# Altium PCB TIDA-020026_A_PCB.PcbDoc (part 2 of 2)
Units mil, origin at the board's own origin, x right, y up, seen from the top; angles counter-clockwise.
Board outline 2952.76 x 2952.76 mil, 2 copper layers (Top Layer, Bottom Layer), stack 62 mil thick; 75 components, 57 nets, 258 pads, 285 vias.
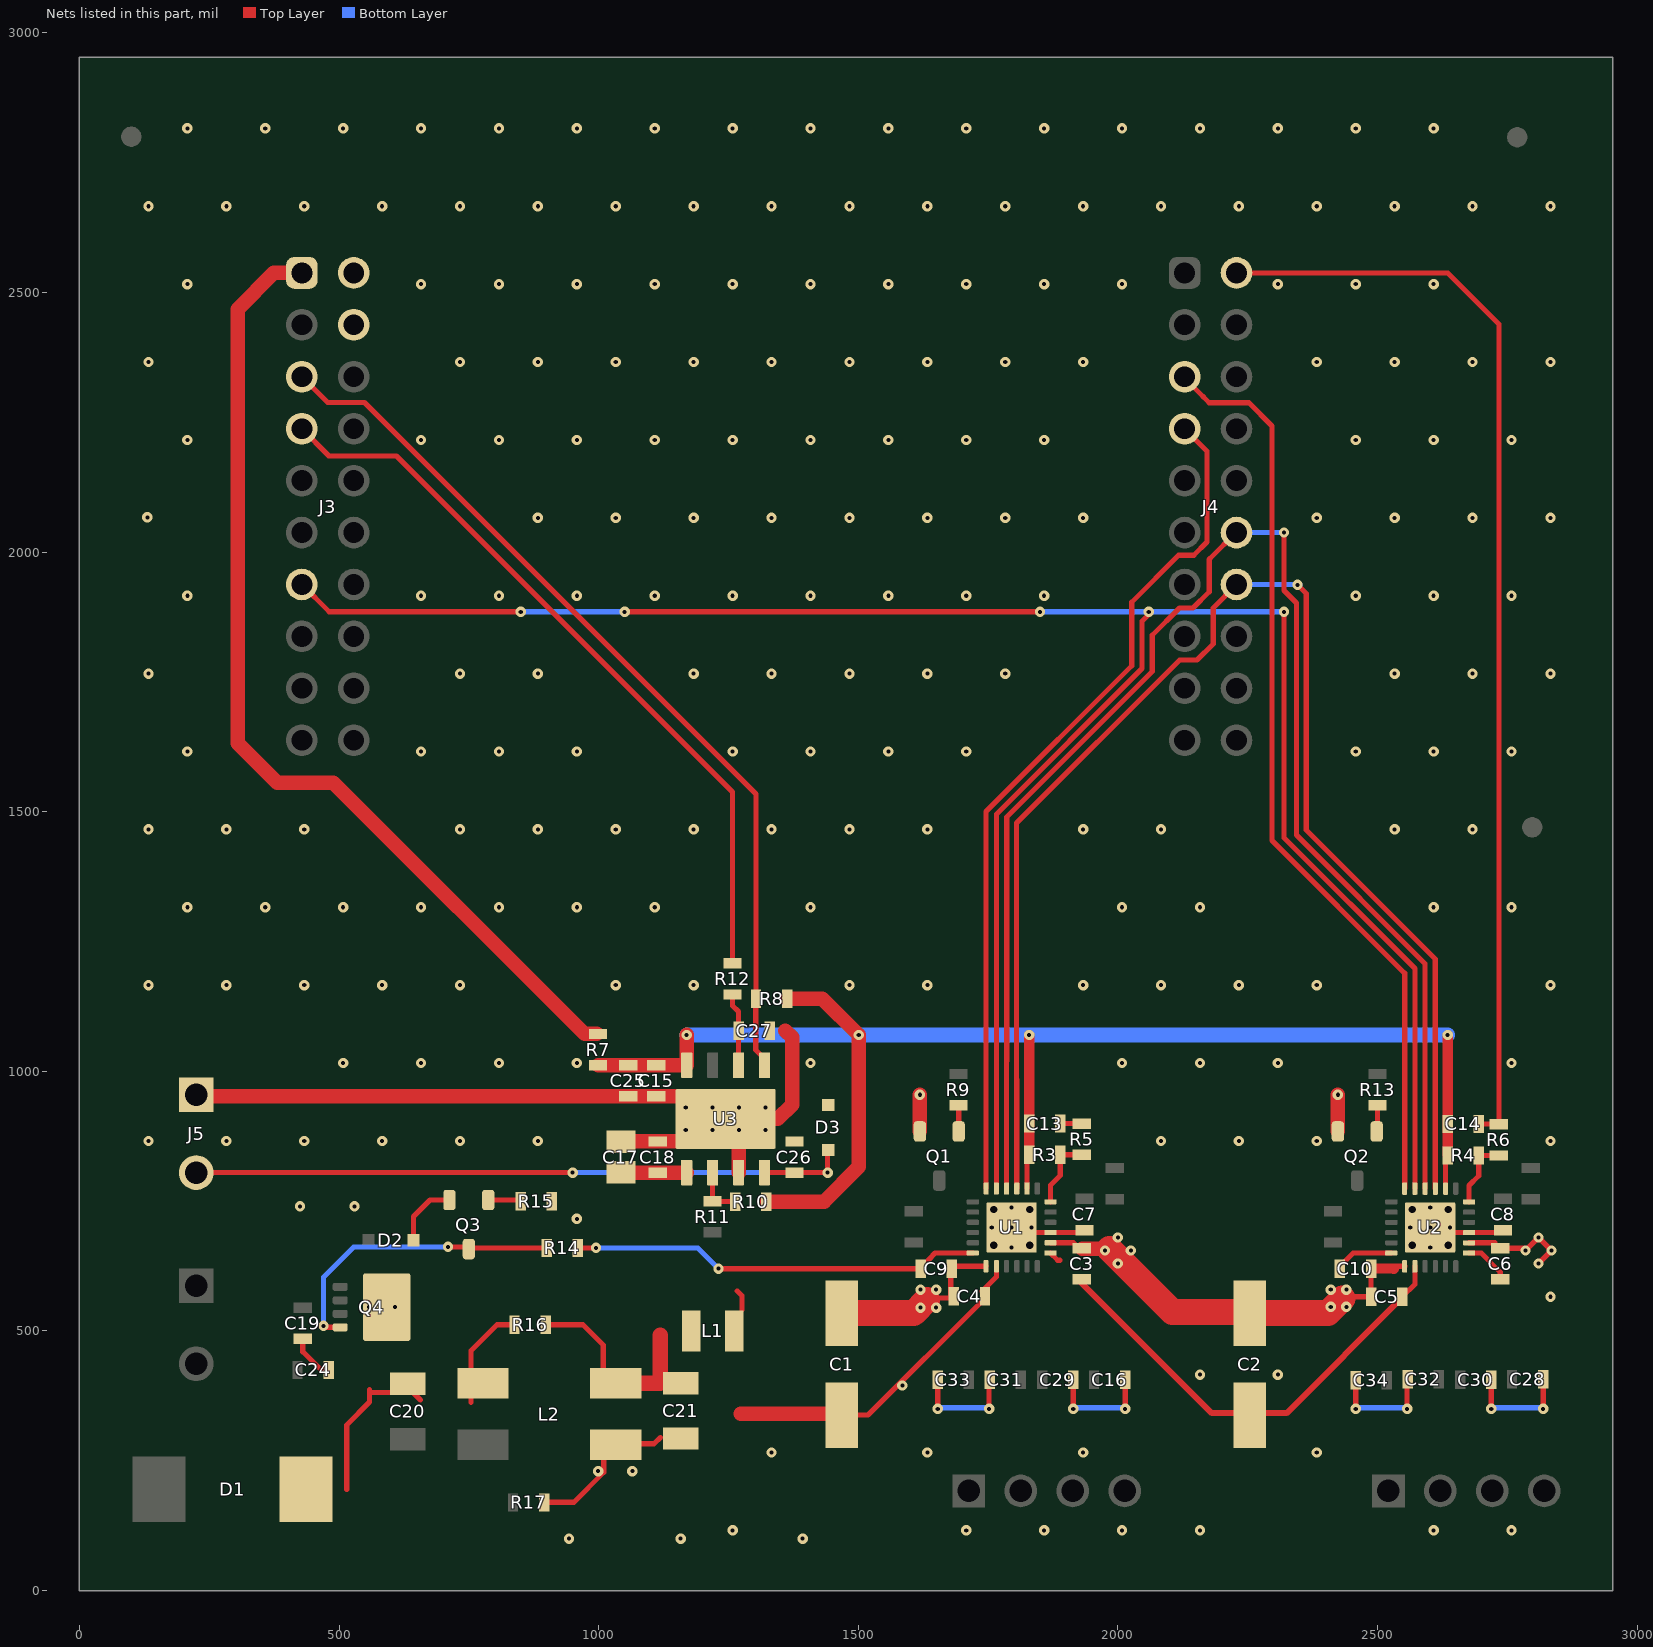
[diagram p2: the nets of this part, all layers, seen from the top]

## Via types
v1: diameter 19.87, hole 7.87, Top Layer to Bottom Layer, tented both sides, 257 vias
v2: diameter 19.68, hole 7.87, Top Layer to Bottom Layer, 16 vias
v3: diameter 26, hole 14, Top Layer to Bottom Layer, 8 vias
v4: diameter 19.68, hole 7.87, Top Layer to Bottom Layer, tented both sides, 4 vias

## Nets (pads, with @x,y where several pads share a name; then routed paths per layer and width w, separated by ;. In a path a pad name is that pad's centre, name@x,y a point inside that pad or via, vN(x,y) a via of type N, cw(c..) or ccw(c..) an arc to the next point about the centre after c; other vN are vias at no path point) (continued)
GND: C1.2 C2.2 C3.2 C4.2 C5.2 C6.2 C7.2 C8.2 C13.2 C14.2 C15.2 C16.1 C17.2 C18.2 C21.2 C25.2 C26.2 C27.2 C28.1 C29.1 C30.1 C31.1 C32.1 C33.1 C34.1 D3.1 J3.4 J4.2 J5.1 L2.3 Q1.2 Q2.2 R5.1 R6.1 R15.1 R17.2 U1.2 U1.7 U1.9 U1.25@1795.47,699.47 U2.2 U2.7 U2.9 U2.25@2601.47,699.34 U3.3 U3.9@1244.52,908.35 | length 7042.7
  Top Layer w10: R17.2@895,170 952,170 1010,228 1010,282.9 1009.95,282.94 1106.8,282.94 1118.85,295 ; U3.9@1222.58,886.42 U3.9@1244.52,908.35 ; C1.2@1480.71,350.29 1493,338 1519,338 C4.2@1743,562 ; v1@1653,352 C33.1@1653,404 ; C4.2@1738.12,576.56 1765.94,604.39 U1.2@1765.94,624.54 ; v1@1752,351 C31.1@1752,403 ; U1.25@1765.94,671.94 U1.25@1794.41,700.41 ; U1.25@1794.5,700.5 U1.25@1795,701 ; U1.25@1795,700 1805.5,689.5 C7.2@1925.63,689.5 ; U1.7@1870.28,650.13 1884.06,636.35 1888.2,636.35 ; C13.2@1886.61,903.2 C13.2@1888.2,901.61 ; C13.2@1890.47,899.34 R5.1@1930.47,899.34 ; v1@1914,353 C29.1@1914,405 ; v1@2014,352 C16.1@2014,405 ; J4.2@2228.47,2537.65 2635.35,2537.65 2734.07,2438.93 2734.07,898.67 C14.2@2695,898.67 ; v1@2458,352 C34.1@2458,404 ; C5.2@2547.62,565.82 2571.94,590.14 U2.2@2571.94,624.54 ; v1@2557,351 C32.1@2557,403 ; U2.25@2612.5,689.5 U2.9@2676.28,689.5 C8.2@2731.63,689.5 ; U2.7@2676.28,650.13 2699.6,650.13 2736.47,613.26 C6.2@2736.47,599.34 ; v1@2719,353 C30.1@2719,405 ; v1@2819,352 C28.1@2819,405
  Top Layer w11.81: C3.2@1921,602 2181,342 2325,342 2547.62,564.62 C5.2@2547.62,565.82 ; C5.2@2545.67,565.82 C5.2@2545.67,568.2 ; U2.25@2571.94,669.94 U2.25@2602,700
  Top Layer w28: J5.1@228,952 C25.2@1057,952 C15.2@1111,952 1200.87,952 U3.9@1244.52,908.35 ; C17.2@1043,864.53 1043.47,865 C18.2@1114,865 1200,865 U3.9@1220.31,885.31 ; U3.9@1268.14,884.73 U3.9@1244.52,908.35 ; U3.3@1269.52,805.01 U3.9@1269.52,883.35 ; 1273.68,340.33 1463.33,340.33 C1.2@1466,343 ; 1359.48,1078.35 1372.47,1065.36 1372.47,935.65 1345.17,908.35 U3.9@1244.52,908.35 ; Q1.2@1618.6,884.24 v1(1618.6,955) ; Q2.2@2423.6,884.24 v1(2423.6,955)
  Bottom Layer w10: v1@1653,352 v1@1750,352 ; v1@1914,352 v1@2014,352 ; v1@2458,352 v1@2555,352 ; v1@2719,352 v1@2819,352
  other v1: 943,100 1158,100 1393,100 1258,116 1708,116 1858,116 2008,116 2158,116 2608,116 2758,116 999,230 1065,230.12 1333,266 1633,266 1933,266 2383,266 1653,350 1752,350 1914,350 2014,350 2458,350 2557,350 2719,350 2819,350 1585,395 2158,416 2308,416 2833,566 958,716 425,740 530,740 133,866 283,866 433,866 583,866 733,866 883,866 2083,866 2233,866 2383,866 2833,866 508,1016 658,1016 808,1016 958,1016 1408,1016 2008,1016 2158,1016 2308,1016 2758,1016 133,1166 283,1166 433,1166 583,1166 733,1166 1033,1166 1183,1166 1483,1166 1633,1166 1933,1166 2083,1166 2233,1166 2383,1166 2833,1166 208,1316 358,1316 508,1316 658,1316 808,1316 958,1316 1108,1316 1408,1316 2008,1316 2158,1316 2608,1316 2758,1316 133,1466 283,1466 433,1466 733,1466 883,1466 1033,1466 1183,1466 1333,1466 1483,1466 1633,1466 1933,1466 2083,1466 2533,1466 2683,1466 208,1616 658,1616 808,1616 958,1616 1258,1616 1408,1616 1558,1616 1708,1616 2458,1616 2608,1616 2758,1616 133,1766 733,1766 883,1766 1183,1766 1333,1766 1483,1766 1633,1766 1783,1766 2533,1766 2683,1766 2833,1766 208,1916 658,1916 808,1916 958,1916 1108,1916 1258,1916 1408,1916 1558,1916 1708,1916 1858,1916 2458,1916 2608,1916 2758,1916 883,2066 1033,2066 1183,2066 1333,2066 1483,2066 1633,2066 1783,2066 1933,2066 2383,2066 2533,2066 2683,2066 2833,2066 131,2067 208,2216 658,2216 808,2216 958,2216 1108,2216 1258,2216 1408,2216 1558,2216 1708,2216 1858,2216 2458,2216 2608,2216 2758,2216 133,2366 733,2366 883,2366 1033,2366 1183,2366 1333,2366 1483,2366 1633,2366 1783,2366 1933,2366 2383,2366 2533,2366 2683,2366 2833,2366 208,2516 658,2516 808,2516 958,2516 1108,2516 1258,2516 1408,2516 1558,2516 1708,2516 1858,2516 2008,2516 2308,2516 2458,2516 2608,2516 133,2666 283,2666 433,2666 583,2666 733,2666 883,2666 1033,2666 1183,2666 1333,2666 1483,2666 1633,2666 1783,2666 1933,2666 2083,2666 2233,2666 2383,2666 2533,2666 2683,2666 2833,2666 208,2816 358,2816 508,2816 658,2816 808,2816 958,2816 1108,2816 1258,2816 1408,2816 1558,2816 1708,2816 1858,2816 2008,2816 2158,2816 2308,2816 2458,2816 2608,2816
  other v2: 1795.47,661.08 2601.47,660.96 1757.09,699.47 1795.47,699.47 1833.86,699.47 2563.09,699.34 2601.47,699.34 2639.86,699.34 1795.47,737.86 2601.47,737.73 1218.93,886.7 1270.11,886.7 1218.93,930.01 1270.11,930.01
  other v3: 1761,665 1830,665 2567,664.87 2636,664.87 1761,734 1830,734 2567,733.87 2636,733.87
  other v4: 1167.75,886.7 1321.29,886.7 1167.75,930.01 1321.29,930.01
"LIN Bus": C26.1 D3.2 J5.2 U3.4 | length 1378.7
  Top Layer w10: J5.2@225,805 v1(950,805) ; U3.4@1320,804.53 U3.4@1319.52,805.01 1372.01,805.01 C26.1@1373,806 ; C26.1@1377,805 v1(1441,805) 1441,847.69 D3.2@1442,848.69
  Bottom Layer w10: v1(950,805) v1(1441,805)
LP_+3V3: J3.1 R7.2 | length 1911.3
  Top Layer w28: J3.1@428.47,2537.65 374.65,2537.65 305,2468 305,1632 381,1556 489,1556 973,1072 R7.2@996,1072
LP_+5V: J3.2
NetC19_2: C19.2 C24.1 | length 89.5
  Top Layer w10: C19.2@430,485 430,460 430.71,460 465.71,425 C24.1@480,425
NetC21_1: C21.1 L1.1 L2.4 R16.2 | length 394.7
  Top Layer w10: R16.2@898,512 970,512 1009,473 L2.4@1009,409.39 ; L2.4@998,396 L2.4@998,398.39
  Top Layer w28: 1118.69,491.69 1119,492
  Top Layer w30: L2.4@1011,402 1013.61,399.39 1118.69,399.39 1118.69,491.69
NetC27_1: C27.1 R12.1 U3.6 | length 141.1
  Top Layer w10: R12.1@1258,1148 1258,1126.52 1269.52,1115 C27.1@1269.52,1078.35 U3.6@1269.52,1011.7
NetD2_2: D2.2 Q3.2 | length 127.9
  Top Layer w10: D2.2@643.31,675 643.31,720.5 675.05,752.24 Q3.2@712.6,752.24
NetQ1_1: Q1.1 R9.2 | length 50.9
  Top Layer w10: R9.2@1693,935 1693.4,934.6 Q1.1@1693.4,884.24
NetQ2_1: Q2.1 R13.2 | length 51.4
  Top Layer w10: Q2.1@2498.4,884.24 2500,885.84 R13.2@2500,935
NetQ3_1: Q3.1 R15.2 | length 63.5
  Top Layer w10: Q3.1@787.4,752.24 847.76,752.24 R15.2@850,750
NetQ3_3: Q3.3 Q4.4 R14.1 | length 583.9
  Top Layer w10: v1(470,510) 472.98,507.02 Q4.4@502.24,507.02 ; v1(710,662) 745.76,662 Q3.3@750,657.76 752.24,660 R14.1@900,660
  Bottom Layer w10: v1(470,510) 470,603.55 528.45,662 v1(710,662)
NetR10_1: R10.1 R11.1 U3.2 | length 100.3
  Top Layer w10: U3.2@1220,804.53 U3.2@1219.52,805.01 1219.52,749.53 1262.94,749.53 R10.1@1263.47,749
RXD: J3.5 R8.1 U3.5 | length 1736.9
  Top Layer w10: J3.5@428.47,2337.65 478.19,2287.93 549.07,2287.93 1303.04,1533.96 R8.1@1303.04,1140 1302.65,1139.6 1302.65,1041 1319.52,1024.13 U3.5@1319.52,1011.7
SCLK: J3.13 U1.17 U2.17 | length 4369.7
  Top Layer w10: J3.13@419,1927 420,1927 J3.13@431.5,1915.5 ; J3.13@428.47,1937.65 481.13,1885 v1(850,1885) ; v1(1050,1885) v1(1850,1885) ; U1.17@1765.94,774.15 1765.94,1495.09 2046.48,1775.62 2046.48,1867 v1@2059.47,1880 ; v1@2320,1880 2320,1450 2571.94,1198.06 U2.17@2571.94,774.15
  Bottom Layer w10: v1(850,1885) v1(1050,1885) ; v1@1049,1880 v1@1050,1881 ; v1(1850,1885) v1(2059.47,1885) v1(2320,1885)
SDI: J4.12 U1.16 U2.16 | length 2930
  Top Layer w10: U1.16@1785.63,774.15 1786,1261 1786,1489.86 2066,1769.86 2066,1840 2118.65,1892.65 2144.83,1892.65 2175.96,1923.79 2175.96,1985.14 ; 2176.96,1987.14 J4.12@2229.47,2039.65 ; v1(2320,2037.93) 2320,1926 2344,1902 2344,1455 2591.63,1207.37 U2.16@2591.63,774.15
  Bottom Layer w10: J4.12@2228.47,2037.65 2228.74,2037.93 v1(2320,2037.93)
SDO: J4.14 U1.15 U2.15 | length 2754.1
  Top Layer w10: U1.15@1805.31,774.15 1805,1199 1805,1478 2119,1792 2152.47,1792 2183.47,1823 2183.47,1892.65 J4.14@2228.47,1937.65 ; v1(2346,1937) 2362.87,1920.13 2362.87,1465.13 2611.31,1216.69 U2.15@2611.31,774.15
  Bottom Layer w10: J4.14@2228.47,1937.65 2350.35,1937.65 v1@2351,1937
STEP_U1: J4.7 U1.18 | length 1674.9
  Top Layer w10: U1.18@1746.26,774.15 1746.26,1500.68 2026.6,1781.02 2026.6,1903.6 2117,1994 2146.18,1994 2171.86,2019.68 2171.86,2194.27 J4.7@2128.47,2237.65
STEP_U2: J4.5 U2.18 | length 1781
  Top Layer w10: J4.5@2128.47,2337.65 2128.47,2335 2164.44,2299.03 2175.82,2287.65 ; 2178.65,2287.65 2252.35,2287.65 2297,2243 2297,1444.32 2552.26,1189.06 U2.18@2552.26,774.15
TXD: J3.7 R12.2 | length 1450
  Top Layer w10: J3.7@428.47,2237.65 480,2186.13 480,2185 611,2185 1258,1538 R12.2@1258,1208
V_supply: C20.1 D1.1 L2.1 Q4.5 Q4.6 Q4.7 Q4.8 Q4.9@592.01,546.02 R16.1 | length 527.9
  Top Layer w10: 514.73,195 514.73,319.21 558.56,363.04 558.56,381.76 ; 558.56,387.53 558.56,381.76 ; C20.1@636.56,387.53 657,367.09 ; C20.1@642.24,381.76 558.56,381.76 ; 754.05,362.05 754.05,401.06 754.05,462.05 804,512 R16.1@838,512
  other v2: 557.76,546.02 607.95,546.02
VCC_3V3: C13.1 C14.1 C15.1 C25.1 R3.2 R4.2 R7.1 R8.2 R10.2 U1.14 U2.14 U3.8 | length 2911.1
  Top Layer w10: U1.14@1825,774.15 R3.2@1825,840.24 ; U2.14@2631,774.15 R4.2@2631,835.6
  Top Layer w20: R3.2@1829,839.34 C13.1@1829,899.34 v1(1829,1070) ; R4.2@2635,839.6 2635,898.02 v1(2635,1070)
  Top Layer w28: R7.1@999,1012 C25.1@1057,1012 C15.1@1111,1012 1169.22,1012 U3.8@1169.52,1011.7 v1(1169.52,1070) ; R10.2@1322.53,749 1434,749 1501,816 v1(1501,1070) 1431,1140 R8.2@1362.57,1140
  Bottom Layer w28: v1(1169.52,1070) v1(1501,1070) v1(1829,1070) v1(2635,1070) v1@2635.41,1070
VCP_U1: C9.2 R14.2 U1.24 | length 788.2
  Top Layer w10: R14.2@960,660 v1(995,660) ; v1(1231,620) C9.2@1617.59,620 ; C9.2@1620,620 1647.85,650.26 U1.24@1720.67,650.26 U1.24@1720.67,650.13
  Bottom Layer w10: v1(995,660) 1191,660 v1(1231,620)
VCP_U2: C10.2 U2.24 | length 116.6
  Top Layer w10: C10.2@2422.78,619.88 2453.15,650.26 2526.67,650.26 U2.24@2526.67,650.13
VM: C1.1 C2.1 C3.1 C4.1 C5.1 C6.1 C9.1 C10.1 C17.1 C18.1 L1.2 U1.1 U1.8 U2.1 U2.8 U3.1 | length 1518.8
  Top Layer w10: C17.1@1043,805.47 1043,804 C17.1@1044,805 ; 1267,577 1276,568 1276,541 ; 1639.22,563.52 1675.57,563.52 1678.12,566.07 1678.12,619.24 1677.47,619.88 1682.13,624.54 U1.1@1746.26,624.54 ; U1.8@1870.28,669.82 1914.23,669.82 C3.1@1924.71,659.34 ; 2435.82,565.82 C5.1@2487.62,565.82 ; C5.1@2485.32,563.52 C5.1@2487.62,565.82 ; C10.1@2487.56,619.88 2487.56,566.44 C5.1@2488,566 ; C10.1@2488,621 C10.1@2488.75,620.25 ; 2517.57,620.25 2514.43,620.25 2518.71,624.54 ; 2531.52,619.88 2536.18,624.54 U2.1@2552.26,624.54 ; U2.8@2676.28,669.82 2726,669.82 ; C6.1@2736.47,659.34 2780.66,659.34 v1(2785,655) v1(2810,680) v1(2835,655) v1(2810,630)
  Top Layer w11.81: C3.1@1924.71,659.34 C3.1@1930.47,659.34 C3.1@1931.55,658.27
  Top Layer w20: C10.1@2488.75,620.25 2514.43,620.25 ; 2517.57,620.25 2531.52,619.88
  Top Layer w28: C17.1@1044,805 C18.1@1114,805 U3.1@1169.52,805.01 ; C3.1@1931.55,658.27 v1@1983.71,658.27
  Top Layer w50: C1.1@1468,534.43 1606.43,534.43 1632,560 ; v1@1983.71,658.27 2104.98,537 C2.1@2248,537 ; C2.1@2254,534.43 2404.43,534.43 2433,563
  other v1: 1620,545 1650,545 2410,546.38 2440,546.38 1620,579.69 1650,579.69 2410,579.69 2440,579.69 2000,630 1975,655 2025,655 2000,680
VREF_U1: R3.1 R5.2 U1.12 | length 140
  Top Layer w10: U1.12@1870.28,748.56 1870.28,780.78 1889,799.5 R3.1@1889,839.34 R5.2@1930.47,839.34
VREF_U2: R4.1 R6.2 U2.12 | length 135.6
  Top Layer w10: U2.12@2676.28,748.56 2676.28,780.28 2695,799 R4.1@2695,838.02 R6.2@2733.42,838.02
pads on no net: FID1.1 FID2.1 FID3.1 J3.3 J3.6 J3.8 J3.9 J3.10 J3.11 J3.12 J3.14 J3.16 J3.17 J3.18 J3.19 J3.20 J4.4 J4.8 J4.10 J4.13 J4.15 J4.17 Q4.9@555,485 Q4.9@555,546.02 Q4.9@555,607.05 Q4.9@578.03,523.58 Q4.9@578.03,568.46 Q4.9@583.94,546.02 U1.25@1770.28,674.27 U1.25@1770.28,724.67 U1.25@1820.67,674.27 U1.25@1820.67,724.67 U2.25@2576.28,674.15 U2.25@2576.28,724.54 U2.25@2626.67,674.15 U2.25@2626.67,724.54 U3.9@1244.52,908.35
copper on no net: | length 10
  Top Layer w10: 2128.47,1727.65 2128.47,1737.65

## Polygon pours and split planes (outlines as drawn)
GND on Top Layer "TOP_LAYER_GND_P104" (solid, remove dead copper, pour order 104): 6.81,2952.29 6.81,674.13 671.81,674.13 875,674.13 875,25.08 2952.76,25.08 2952.04,2948.01
VM on Top Layer "TOP_LAYER_VM_P088" (solid, remove dead copper, pour order 88): 2847,695 2847,620 2764.1,620.9 2717.79,667.21 2717.79,674.77 2765.83,674.77 2781,695
BAT+ on Top Layer "TOP_LAYER_BAT+_P086" (solid, remove dead copper, pour order 86): 25,514 501,514 501,473 654.35,473 654.35,635.38 365,635.38 25,635.38
NetC21_1 on Top Layer "TOP_LAYER_NETC21_1_P082" (solid, remove dead copper, pour order 82): 875,635 875,350 1205,350 1205,635
BAT- on Top Layer "TOP_LAYER_BAT-_P094" (solid, remove dead copper, pour order 94): 251,851 376,851 376,783 251,783
BAT- on Top Layer "TOP_LAYER_BAT-_P096" (solid, remove dead copper, pour order 96): 24.34,507 435.66,507 434.53,402.43 451,402.43 451,119 583,251 583,338 850,338 850,23 25.4,23
VM on Top Layer "TOP_LAYER_VM_P078" (solid, pour order 78): 1496.3,410 1220.14,410 1220.14,537.93 1010.76,747.31 1010.76,833 1180,833 1180.67,642.58 1220.14,603.1 1633,603.1 1633,636 1752,636 1752,615.05 1546.95,410
V_supply on Top Layer "TOP_LAYER_V_SUPPLY_P090" (solid, remove dead copper, pour order 90): 545,635 850,635 850,350 575.23,350 575.23,221.86 486.45,133.07 390,133.07 390,258.69 461,329.69 461,464.03 545,464.03
VM on Top Layer "TOP_LAYER_VM_P077" (solid, pour order 77): 1854.18,662.52 1898.98,662.52 1939.49,622 2126.49,435 2381.4,435 2584.74,638.34 2445.04,638.34 2445.04,592.24 2409.55,592.24 2409.55,697.27 1989.84,697.27 1965.79,677.52 1854.18,677.52
VM on Bottom Layer "BOTTOM_LAYER_VM_P108" (solid, remove dead copper, pour order 108): 2392,600 2392,525 2725,525 2860,660 2800,720 2680,600
VM on Bottom Layer "BOTTOM_LAYER_VM_P110" (solid, remove dead copper, pour order 110): 1590,600 1590,525 1915,525 2050,660 1990,720 1870,600
BAT- on Bottom Layer "BOTTOM_LAYER_BAT-_P112" (solid, remove dead copper, pour order 112): 25.49,633.87 25.49,25.49 850,25.49 850,505 850,633.87
GND on Bottom Layer "BOTTOM_LAYER_GND_P114" (solid, remove dead copper, pour order 114): 25,2952.76 25,674.37 875,674.37 875,0 2952.76,0 2952.76,2952.76

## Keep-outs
Bottom Layer:
  region: 185.47,2616.65
Keep-Out Layer:
  text ".Layer_Name" at 577,-858.49 h60

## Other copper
Top Layer:
  pour cut-out: 2551.26,646.59 2653.74,646.59 2653.74,661.97 2663.2,661.7 2663.2,638.34 2551.26,638.34
  pour cut-out: 1746.26,646.59 1848.74,646.59 1848.74,661.97 1858.2,661.7 1858.2,638.34 1746.26,638.34
  text ".Layer_Name" at 577,-858.49 h60
Bottom Layer:
  text ".Layer_Name" at 577,-858.49 h60

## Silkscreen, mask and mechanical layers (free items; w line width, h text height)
Top Overlay:
  text "LP_5V" at 590,2545 h30
  text "LP_3V3" at 170,2540 h30
  text "GND" at 2295,2537.65 h30
  text "EN" at 1990,2535.16 h30
  text "/SLEEP_U1" at 1813,2427 h30
  text "GND" at 598.47,2417.65 h30
  text "/SCS_U2" at 2293.47,2317.65 h30
  text "STEP_U2" at 1867.47,2315 h30
  text "RXD" at 270,2310 h30
  text "STEP_U1" at 1870,2235 h30
  text "TXD" at 270,2210 h30
  text "DRVOFF_U1" at 1810,2118 h30
  text "SDI" at 2346,2013 h30
  text "DIR_U1" at 1900,2007.34 h30
  text "SDO" at 2370,1935 h30
  text "SCLK" at 243.47,1908.95 h30
  text "/RST" at 235,1800 h30
  text "DRVOFF_U2" at 1804.26,1717.65 h30
  text "/SCS_U1" at 2299,1717 h30
  text "DIR_U2" at 2300,1635 h30
  text "/SLEEP_U2" at 1804.26,1617.65 h30
  text "GND" at 24,1060 h30 r270
  text "LINBUS" at 27,880 h30 r270
  text "BAT+" at 30,629.57 h30 r270
  text "BAT-" at 30,474.69 h30 r270
  text "A1" at 2305,85 h30 r90
  text "A2" at 2345,85 h30 r90
  text "B2" at 2385,85 h30 r90
  text "B1" at 2425,85 h30 r90
  text "A1" at 1500,81 h30 r90
  text "A2" at 1540,81 h30 r90
  text "B2" at 1580,81 h30 r90
  text "B1" at 1620,81 h30 r90
  text ".Layer_Name" at 577,-858.49 h60
Bottom Overlay:
  text ".Layer_Name" at 577,-858.49 h60
Top Paste:
  text ".Layer_Name" at 577,-858.49 h60
Bottom Paste:
  text ".Layer_Name" at 577,-858.49 h60
Top Solder:
  text ".Layer_Name" at 577,-858.49 h60
  text ".Layer_Name" at 577,-858.49 h60
Bottom Solder:
  text ".Layer_Name" at 577,-858.49 h60
Drill Guide:
  text ".Layer_Name" at 577,-858.49 h60
M1 Board Outline:
  the board outline again, w10
  text ".Layer_Name" at 577,-858.49 h60
M2 Board Dimensions:
  rectangle: 0,-275 125,-150
  rectangle: 125,-400 500,-275
  lines w7: 0,-275 1000,-275 ; 125,-400 125,-150 ; 250,-400 250,-150 ; 500,-400 500,-150 ; 750,-400 750,-150 ; 0,-400 1000,-400 1000,-150 0,-150 0,-400
  text ".Layer_Name" at 577,-858.49 h60
M3 3D STEP Top:
  text ".Layer_Name" at 577,-858.49 h60
M4 3D STEP Bottom:
  text ".Layer_Name" at 577,-858.49 h60
M5 Assembly Top:
  lines w10: -292,-930.17 6308,-930.17 ; -292,-726.83 6310,-726.83 ; -292,-523.5 -292,-1133.5 3713,-1133.5 6310,-1133.5 6310,-523.5 -291.5,-523.5 -291.5,-1133.5 1284,-1133.5 ; 2173,-1133.5 2173,-523.5 ; 3440,-726.83 3440,-523.5 ; 4280,-726.83 4280,-523.5 ; 4902,-1140 4902,-937.17
  text "COMPONENTS MARKED 'DNP' SHOULD NOT BE POPULATED." at 1153.5,-318.5 h60
  text "ASSEMBLY VARIANT:" at 1153,-434 h60
  text ".VariantName" at 2189,-434 h60
  text "PCB VIEWED FROM TOP SIDE" at -228.5,-655.67 h60
  text "BOARD #:" at 2248,-655.67 h60
  text ".PRJ_Number" at 2793.5,-655.67 h60
  text "REV:" at 3638,-655.67 h60
  text ".PCB_Rev" at 3929.5,-655.67 h60
  text "SVN REV:" at 4476,-655.67 h60
  text ".VersionControl_RevNumber" at 4982,-655.67 h60
  text "TID #:" at 2248,-859 h60
  text ".TID" at 2793.5,-859 h60
  text "PLOT NAME =" at -228.5,-1064.34 h60
  text ".plot_File_Name" at 577,-1064.34 h60
  text "GENERATED    :" at 2250,-1064.34 h60
  text ".Print_Date" at 3119.5,-1064.34 h60
  text ".Print_Time" at 3848.5,-1064.34 h60
  text "TEXAS INSTRUMENTS" at 5113,-1064.34 h60
M6 Assembly Bottom:
  lines w10: -292.5,-727.33 6309.5,-727.33 ; -290.5,-930.67 6309.5,-930.67 ; 1115.5,-1140.5 1115.5,-937.67 ; 1737.5,-727.33 1737.5,-524 ; 2577.5,-727.33 2577.5,-524 ; 3844.5,-1134 3844.5,-524 ; 4733.5,-1134 6309,-1134 6309,-524 -292.5,-524 -292.5,-1134 2304.5,-1134 6309.5,-1134 6309.5,-524
  text "COMPONENTS MARKED 'DNP' SHOULD NOT BE POPULATED." at 6102,-318 h60
  text ".VariantName" at 5058,-434 h60
  text "ASSEMBLY VARIANT:" at 6097,-434 h60
  text ".VersionControl_RevNumber" at 1035.5,-656.17 h60
  text "SVN REV:" at 1541.5,-656.17 h60
  text ".PCB_Rev" at 2088,-656.17 h60
  text "REV:" at 2379.5,-656.17 h60
  text ".PRJ_Number" at 3224,-656.17 h60
  text "BOARD #:" at 3769.5,-656.17 h60
  text "PCB VIEWED FROM BOTTOM SIDE" at 6246,-656.17 h60
  text ".TID" at 3224,-859.5 h60
  text "TID #:" at 3769.5,-859.5 h60
  text "TEXAS INSTRUMENTS" at 904.5,-1064.84 h60
  text ".Print_Time" at 2169,-1064.84 h60
  text ".Print_Date" at 2898,-1064.84 h60
  text "GENERATED    :" at 3767.5,-1064.84 h60
  text ".plot_File_Name" at 5440.5,-1064.84 h60
  text "PLOT NAME =" at 6246,-1064.84 h60
M9 Title Sheet:
  drawing of 57 lines, arcs and shapes, not listed
  text "1" at 739.84,8036.5 h70
  text "2" at 3235.5,8036.5 h70
  text "3" at 5724.84,8036.5 h70
  text "4" at 8231.51,8036.5 h70
  text "5" at 10730.5,8036.5 h70
  text "6" at 13235.5,8036.5 h70
  text "A" at -416.5,6893.5 h70
  text "A" at 14383.5,6893.5 h70
  text "B" at -416.5,4513.5 h70
  text "B" at 14383.5,4513.5 h70
  text "C" at -416.5,2138.5 h70
  text "C" at 14383.5,2138.5 h70
  text "PROJECT TITLE:" at 11343.5,277.5 h45
  text ".PRJ_Title" at 11393.5,144.17 h70
  text "DESIGNED FOR:" at 11343.5,-23.5 h45
  text ".PRJ_Customer" at 11393.5,-163.5 h70
  text "D" at -416.5,-231.5 h70
  text "D" at 14383.5,-231.5 h70
  text "FILE NAME:" at 11343.5,-323.5 h45
  text ".PCB_File_Name_No_Path" at 11393.5,-443.5 h70
  text "Texas Instruments (TI) and/or its licensors do not warrant the accuracy or completeness of this specification" at 6374,-605.34 h45
  text "ENGINEER:" at 11343.5,-613.5 h45
  text "LAYOUT BY:" at 12848.5,-613.5 h45
  text "or any information contained therein. TI and/or its licensors do not warrant that this design will meet" at 6329.01,-718 h45
  text ".PRJ_Engineer" at 11393.5,-768.49 h70
  text ".PCB_Layout" at 12899,-768.49 h70
  text "the specifications, will be suitable for your application or fit for any particular purpose, or will operate in" at 6329.01,-830.67 h45
  text ".Layer_Name" at 577,-858.49 h60
  text "ALTIUM DESIGNER VERSION:" at 12848.5,-923.5 h45
  text "an implementation. TI and/or its licensors do not warrant that the design is production worthy. You should" at 6329.01,-943.33 h45
  text "completely validate and test your design implementation to confirm the system functionality for your application." at 6374,-1056 h45
  text ".print_Scale" at 11393.5,-1056.83 h70
  text ".Application_BuildNumber" at 12899,-1056.83 h70
  text "1" at 739.84,-1263.5 h70
  text "2" at 3235.5,-1263.5 h70
  text "3" at 5724.84,-1263.5 h70
  text "4" at 8231.51,-1263.5 h70
  text "5" at 10730.5,-1263.5 h70
  text "6" at 13235.5,-1263.5 h70
M10 Fab Notes:
  drawing of 189 lines, arcs and shapes, not listed
  text "DESIGN INFORMATION" at 12382.02,6356.17 h60
  text "MIN. TRACK WIDTH:" at 11737.46,6224.05 h60
  text "8" at 12833.7,6224.05 h60
  text "MIL" at 12988.46,6224.05 h60
  text "MIN. CLEARANCE:" at 11737.46,6099.92 h60
  text "0.2" at 12773.7,6099.93 h60
  text "mm" at 12988.46,6099.92 h60
  text "MIN. VIA PAD SIZE:" at 11737.46,5975.8 h60
  text "24" at 12803.71,5975.8 h60
  text "MIL" at 12988.46,5975.8 h60
  text "0.05mm (2MIL)" at 12432.46,5845.9 h60
  text "MINIMUM ANNULAR RING" at 11408.23,5837.67 h60
  text "EXTERNAL" at 13140.46,5837.67 h60
  text "PER" at 11608.23,5727.55 h60
  text "IPC-D-275 CLASS 2 LEVEL C" at 11828.23,5727.54 h60
  text "MIL, HOLES" at 13316.46,5627.07 h60
  text "+/-" at 12924,5618.48 h60
  text "+/-" at 13778,5618.48 h60
  text "REGISTRATION TOLERANCES:" at 11408.23,5617.42 h60
  text "METAL" at 12608,5617.42 h60
  text "5" at 13184.2,5617.42 h60
  text "3" at 14017.2,5617.42 h60
  text "MIL" at 14133.46,5617.42 h60
  text "HOLE SIZE TOLERANCE (UNLESS OTHERWISE SPECIFIED):" at 11408.23,5519.1 h60
  text "+/-" at 13778,5516.23 h60
  text "3" at 14017.2,5515.17 h60
  text "MIL" at 14133.46,5515.17 h60
  text "MATERIAL:" at 11333.46,5377.52 h60
  text "FR-4 High Tg" at 12319.9,5249 h60
  text "X" at 12175.46,5241.01 h60
  text "FR-408" at 11754.46,5236.49 h60
  text "OTHER" at 13242.46,5236.49 h60
  text "62 MIL (1.6mm) +/-10%" at 12074.56,5093.46 h60
  text "X" at 11954.46,5091.01 h60
  text "THICKNESS:" at 11408.23,5085.24 h60
  text "OTHER" at 13359.46,5085.24 h60
  text "TOLERANCE:" at 11408.23,4946.92 h60
  text "X" at 12256.46,4946.92 h60
  text "ANSI IPC-6012 TYPE 3 CLASS 2" at 12434.48,4946.92 h60
  text "OTHER +/-" at 12434.46,4802.73 h60
  text "BOW & TWIST:" at 11408.23,4657.54 h60
  text "X" at 12256.46,4657.54 h60
  text "ANSI IPC-6012 TYPE 3 CLASS 2" at 12434.48,4657.54 h60
  text "OTHER +/-" at 12434.46,4510.85 h60
  text "DRILLING:" at 11333.46,4380.23 h60
  text "NC_DRILL FILES" at 13094.46,4275.04 h60
  text "REFERENCE:" at 11408.23,4271.1 h60
  text "X" at 12065.46,4271.01 h60
  text "AS SHOWN" at 12243.46,4271.1 h60
  text "X" at 12966.46,4271.1 h60
  text "OTHER" at 13392.46,4128.85 h60
  text "PTH COPPER THICKNESS:" at 11407.91,4125.32 h60
  text "X" at 12547.14,4125.32 h60
  text "20-30 um" at 12675.14,4125.32 h60
  text "BOARD FINISH:" at 11333.46,3977.73 h60
  text "SILKSCREEN:" at 11488.68,3867.6 h60
  text "X" at 12446.46,3867.6 h60
  text "TOP" at 12563.46,3867.6 h60
  text "X" at 12956.46,3867.6 h60
  text "BOTTOM" at 13074.46,3867.6 h60
  text "SILKSCREEN COLOR:" at 11488.68,3712.41 h60
  text "X" at 12445.46,3712.41 h60
  text "WHITE" at 12563.46,3712.41 h60
  text "OTHER" at 13074.46,3712.41 h60
  text "X" at 12576.46,3568.96 h60
  text "GREEN" at 12694.46,3568.96 h60
  text "OTHER" at 13312.46,3568.96 h60
  text "SOLDER RESIST COLOR:" at 11488.68,3562.1 h60
  text "X" at 12576.46,3414.71 h60
  text "MATTE" at 12694.46,3414.71 h60
  text "SEMI-GLOSS" at 13312,3414.07 h60
  text "IMMERSION GOLD (ENIG)" at 12394.46,3241.94 h60
  text "ENEPIG" at 13732,3234.72 h60
  text "SURFACE FINISH:" at 11333.46,3233.72 h60
  text "X" at 12216.46,3233.72 h60
  text "IMM. TIN/SILVER OR EQUIV" at 11663,3096.4 h60
  text "OTHER" at 13094.46,3092.47 h60
  text "ARRAY/PANEL:" at 11333.46,2937.09 h60
  text "CUT AND TRIM PER M1 BOARD OUTLINE" at 12394.46,2928.87 h60
  text "N.C. ROUTE" at 12394.46,2792.9 h60
  text "X" at 13082.46,2792.9 h60
  text "V. SCORE" at 13260.46,2792.9 h60
  text "CERTIFICATION:" at 11333.46,2663.77 h60
  text "MATERIALS AND WORKMANSHIP FOR ALL PCBS" at 12058.46,2663.77 h60
  text "TO MEET OR EXCEED THE REQUIREMENTS OF:" at 12058.46,2569.71 h60
  text "X" at 11695.97,2441.08 h60
  text "ANSI IPC-A-600F CLASS ->" at 11823.96,2441.08 h60
  text "X" at 13471.97,2441.08 h60
  text "2" at 13581.96,2441.08 h60
  text "1" at 13266.96,2439.58 h60
  text "3" at 13935.96,2439.58 h60
  text "X" at 12507.97,2293.39 h60
  text "RoHS" at 12635.96,2293.39 h60
  text "OTHER" at 13280.36,2293.39 h60
  text "PER ORDER" at 13677.42,2293.39 h60
  text "ALL BOARDS MUST MEET OR EXCEED UL94-V0 REQUIREMENTS." at 11361,2139.57 h60
  text "PCB MUST BEAR THE UL94V-0 UL REGISTERED MATERIAL ID NUMBER" at 11361,2023.5 h60
  text "ADDITIONAL REQUIREMENTS:" at 11333.46,1854.08 h60
  text "MICROSECTION:" at 11408.23,1746.95 h60
  text "YES" at 12313.96,1746.95 h60
  text "REQUIRED" at 13175.46,1602.62 h60
  text "BARE BOARD ELEC. TEST:" at 11408.23,1599.76 h60
  text "NONE" at 12713.96,1599.76 h60
  text "X" at 13057.46,1599.76 h60
  text "PER ORDER" at 13767.46,1599.76 h60
  text "XX MIL VIAS REQUIRE NON-CONDUCTIVE FILL AND PLANARIZE" at 11576.38,1394.82 h59
  text "XX MIL VIAS REQUIRE CONDUCTIVE FILL AND PLANARIZE" at 11584.38,1290.84 h60
  text "OUTER XX MIL TRACES REQUIRE 50 OHM SINGLE-ENDED IMPEDANCE" at 11583.39,1127.46 h58
  text "LAYER 2 & 3 (INNER LAYERS) XX MIL WIDE, XX MIL SPACE / TRACES REQUIRE 100 OHM DIFFERENTIAL IMPEDANCE" at 11575.39,891.74 h60
  text ".Layer_Name" at 577,-858.49 h60
M11 Gerber Information:
  lines w10: -292,-930.17 6308,-930.17 ; -292,-726.83 6310,-726.83 ; -292,-523.5 -292,-1133.5 3713,-1133.5 6310,-1133.5 6310,-523.5 -291.5,-523.5 -291.5,-1133.5 1284,-1133.5 ; 2173,-1133.5 2173,-523.5 ; 3440,-726.83 3440,-523.5 ; 4280,-726.83 4280,-523.5 ; 4902,-1140 4902,-937.17
  text "ALL ARTWORK VIEWED FROM TOP SIDE" at -228.5,-655.67 h60
  text "BOARD #:" at 2248,-655.67 h60
  text ".PRJ_Number" at 2793.5,-655.67 h60
  text "REV:" at 3638,-655.67 h60
  text ".PCB_Rev" at 3929.5,-655.67 h60
  text "SVN REV:" at 4476,-655.67 h60
  text ".VersionControl_RevNumber" at 4982,-655.67 h60
  text "LAYER NAME =" at -228.5,-858.49 h60
  text "TID #:" at 2248,-859 h60
  text ".TID" at 2793.5,-859 h60
  text "PLOT NAME =" at -228.5,-1064.34 h60
  text ".plot_File_Name" at 577,-1064.34 h60
  text "GENERATED    :" at 2250,-1064.34 h60
  text ".Print_Date" at 3119.5,-1064.34 h60
  text ".Print_Time" at 3848.5,-1064.34 h60
  text "TEXAS INSTRUMENTS" at 5113,-1064.34 h60
M12 Stackup:
  drawing of 191 lines, arcs and shapes, not listed
  text "Layer" at 9710.09,7545 h60
  text "Name" at 10120,7545 h60
  text "Material" at 11049.74,7545 h60
  text "Thickness" at 11909.51,7545 h60
  text "Constant" at 12559.35,7545 h60
  text "Board Layer Stack" at 13129.21,7545 h60
  text "1" at 9710.09,7425 h60
  text "Top Overlay" at 10120,7425 h60
  text "2" at 9710.09,7305 h60
  text "Top Solder" at 10120,7305 h60
  text "Solder Resist" at 11049.74,7305 h60
  text "0.40mil" at 11909.51,7305 h60
  text "3.5" at 12559.35,7305 h60
  text "3" at 9710.09,7185 h60
  text "Top Layer" at 10120,7185 h60
  text "Copper" at 11049.74,7185 h60
  text "1.40mil" at 11909.51,7185 h60
  text "4" at 9710.09,7065 h60
  text "Dielectric1" at 10120,7065 h60
  text "FR-4" at 11049.74,7065 h60
  text "59.20mil" at 11909.51,7065 h60
  text "4.8" at 12559.35,7065 h60
  text "5" at 9710.09,6945 h60
  text "Bottom Layer" at 10120,6945 h60
  text "Copper" at 11049.74,6945 h60
  text "1.40mil" at 11909.51,6945 h60
  text "6" at 9710.09,6825 h60
  text "Bottom Solder" at 10120,6825 h60
  text "Solder Resist" at 11049.74,6825 h60
  text "0.40mil" at 11909.51,6825 h60
  text "3.5" at 12559.35,6825 h60
  text "7" at 9710.09,6705 h60
  text "Bottom Overlay" at 10120,6705 h60
  text ".Layer_Name" at 577,-858.49 h60
M13 Component Bodies Top:
  text ".Layer_Name" at 577,-858.49 h60
M14 Component Bodies Bottom:
  text ".Layer_Name" at 577,-858.49 h60
M15 Courtyards Top:
  text ".Layer_Name" at 577,-858.49 h60
M16 Courtyards Bottom:
  text ".Layer_Name" at 577,-858.49 h60
Drill Drawing:
  circle w10: c3368.72,2618.96 r27.63
  lines w10: 3341.09,2342.7 3396.34,2342.7 3396.34,2397.95 3341.09,2397.95 3341.09,2342.7 ; 3341.09,2522.27 3396.34,2522.27 3368.72,2467.02 3341.09,2522.27 ; 3341.09,2729.47 3354.9,2729.47 3368.72,2715.66 3382.53,2729.47 3396.34,2729.47 3382.53,2743.28 3396.34,2757.1 3382.53,2757.1 3368.72,2770.91 3354.9,2757.1 3341.09,2757.1 3354.9,2743.28 3341.09,2729.47
  lines w12: 3291,2305.4 6522.49,2305.4 ; 3291,2802.68 6522.49,2802.68 ; 3628.86,2181.08 3628.86,2927 ; 3960.86,2181.08 3960.86,2927 ; 4597.43,2181.08 4597.43,2927 ; 4856.57,2181.08 4856.57,2927 ; 5231.72,2181.08 5231.72,2927 ; 5956.05,2181.08 5956.05,2927 ; 3291,2181.08 6522.49,2181.08 6522.49,2927 3291,2927 3291,2181.08
  text "Symbol" at 3365.59,2839.98 h72
  text "Quantity" at 3666.16,2839.98 h72
  text "Finished Hole Size" at 3998.16,2839.98 h72
  text "Plated" at 4634.72,2839.98 h72
  text "Hole Type" at 4893.86,2839.98 h72
  text "Drill Layer Pair" at 5269.02,2839.98 h72
  text "Hole Tolerance" at 5993.35,2839.98 h72
  text "277" at 3666.16,2715.66 h60
  text "7.87mil (0.200mm)" at 3998.16,2715.66 h60
  text "PTH" at 4634.72,2715.66 h60
  text "Round" at 4893.86,2715.66 h60
  text "Top Layer - Bottom Layer" at 5269.02,2715.66 h60
  text "8" at 3666.16,2591.34 h60
  text "14.00mil (0.356mm)" at 3998.16,2591.34 h60
  text "PTH" at 4634.72,2591.34 h60
  text "Round" at 4893.86,2591.34 h60
  text "Top Layer - Bottom Layer" at 5269.02,2591.34 h60
  text "40" at 3666.16,2467.02 h60
  text "40.00mil (1.016mm)" at 3998.16,2467.02 h60
  text "PTH" at 4634.72,2467.02 h60
  text "Round" at 4893.86,2467.02 h60
  text "Top Layer - Bottom Layer" at 5269.02,2467.02 h60
  text "12" at 3666.16,2342.7 h60
  text "43.31mil (1.100mm)" at 3998.16,2342.7 h60
  text "PTH" at 4634.72,2342.7 h60
  text "Round" at 4893.86,2342.7 h60
  text "Top Layer - Bottom Layer" at 5269.02,2342.7 h60
  text "337 Total" at 3666.16,2218.38 h60
  text ".Layer_Name" at 577,-858.49 h60
M17 Embedded Cavity:
  text ".Layer_Name" at 577,-858.49 h60
M18 Embedded Assembly:
  text ".Layer_Name" at 577,-858.49 h60
M19 Embedded Keepout:
  text ".Layer_Name" at 577,-858.49 h60

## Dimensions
0,-400 to 1000,-400 on M2 Board Dimensions
0,0 to 0,2952.76 on M2 Board Dimensions
0,0 to 2952.76,0 on M2 Board Dimensions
